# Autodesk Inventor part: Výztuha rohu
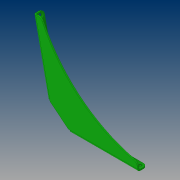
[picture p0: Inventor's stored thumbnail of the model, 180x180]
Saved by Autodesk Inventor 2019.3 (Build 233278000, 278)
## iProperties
Created: 2019-02
Part Number: Výztuha rohu
Material: Ocel, měkká, svařovaná
Document SubType Name: Plech
Designer: B-hon
Density: 7.85 g/cm^3
Sheet Metal Rule: Výchozí_mm
Appearance: Tmavě zelená
Author: B-hon
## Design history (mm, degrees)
node "Plocha2"
  sketch "Náčrt1"
    geometry: L1 (0, 0)-(-10.396, 48.907); L2 (0, 0)-(50, 0); L3 (-51.978, 244.537)-(-37.306, 247.656); L4 (0, 0)-(226.092, 279.201); L5 (250, 0)-(250, 15); L6 (50, 0)-(50, -8); L7 (50, -8)-(250, -8); L8 (250, -8)-(250, 0); L9 (-10.396, 48.907)-(-18.221, 47.244); L10 (-18.221, 47.244)-(-59.803, 242.874); L11 (-59.803, 242.874)-(-51.978, 244.537); L12 (-51.978, 244.537)-(148.022, 244.537); A1 r 400 centre (329.584, 407.003) between (-37.306, 247.656) and (250, 15)
    constraints: 24 end point, 2 horizontal, 2 parallel, 2 point on circle, 1 centre point, 1 perpendicular, 1 point on line, 1 vertical
    dimensions: "d0" = 250 distance of L1.start L5.start; "d1" = 250 distance of L1.start L3.start; "d2" = 102 deg angle of L2 L1; "d3" = 15 distance of L3.start L3.end; "d5" = 51 deg angle of L2 L4 (= 0.5 x d2); "d6" = 400 radius of A1; "d39" = 200 distance of L7.end L6.end; "d40" = 8 distance of L2.end L6.end; "d41" = 200 distance of L1.end L3.start; "d43" = 8 distance of L1.end L9.end (= d40)
node "Obruba4"
node "Obruba5"
chamfer "Zkosení1" distance "d68" = 45; stored, may be unused: second distance "d69" = 2, angle "d70" = 45 deg
fillet "Zaoblení3" dims "d71" = 10
fillet "Zaoblení4" dims "d72" = 10
fillet "Zaoblení5" dims "d73" = 15
sketch "Náčrt9"
  geometry: A1 r 10 centre (190, 10) between (200, 10) and (190, 20) reference; A2 r 10 centre (10, 10) between (10, 20) and (0, 10) reference; 3 further points
  constraints: 2 coincident
hole "Díra1" sketch "Náčrt9" at (190, 10), (10, 10) diameter "d74" = 8.4; stored, may be unused: countersink angle "d78" = 90 deg, drill point angle "d80" = 118 deg; dims "d75" = 12, "d76" = 15.4, "d77" = 2, "d79" = 4 (= Tloušťka)
sketch "Náčrt10"
  geometry: A1 r 10 centre (10, -10) between (20, -10) and (10, 0) reference; A2 r 10 centre (10, -190) between (10, -200) and (20, -190) reference; 3 further points
  constraints: 2 coincident
hole "Díra2" sketch "Náčrt10" at (10, -10), (10, -190) diameter "d81" = 8.4; stored, may be unused: countersink angle "d85" = 90 deg, drill point angle "d87" = 118 deg; dims "d82" = 12, "d83" = 15.4, "d84" = 2, "d86" = 4 (= Tloušťka)
sketch "Náčrt11"
  geometry: L1 (190, 20)-(10, 20) reference; L2 (200, 0)-(200, 10) reference; 2 further points
  dimensions: "d88" = 10 distance from line of L1 point (140, 10); "d89" = 60 distance from line of L2 point (140, 10)
hole "Díra3" sketch "Náčrt11" at (140, 10) diameter "d90" = 8.4; stored, may be unused: countersink angle "d94" = 90 deg, drill point angle "d96" = 118 deg; dims "d91" = 12, "d92" = 15.4, "d93" = 2, "d95" = 4 (= Tloušťka)
sketch "Náčrt12"
  geometry: L1 (0, 0)-(10, 0) reference; L2 (20, -190)-(20, -10) reference; 2 further points
  dimensions: "d97" = 60 distance from line of L1 point (10, -60); "d98" = 10 distance from line of L2 point (10, -60)
hole "Díra4" sketch "Náčrt12" at (10, -60) diameter "d99" = 8.4; stored, may be unused: countersink angle "d103" = 90 deg, drill point angle "d105" = 118 deg; dims "d100" = 12, "d101" = 15.4, "d102" = 2, "d104" = 4 (= Tloušťka)
node "Těleso2"
feature "Deska5" dims "d44" = 4 (= Tloušťka)
sketch "Náčrt7"
  geometry: L1 through (100, 0) direction (-1, 0); L2 through (0, -14) direction (0, -1); L3 (0, -28)-(200, -28); L4 (200, -28)-(200, 0)
  constraints: 6 end point, 1 horizontal, 1 perpendicular, 1 vertical
feature "Deska6" dims "d44" = 4 (= Tloušťka), "d46" = 4 (= ŠířkaVýštipu), "d47" = 2 (= HloubkaVýštipu), "d48" = 8 (= MinimálníZbytek), "d49" = 4 (= PřechodovýPoloměr), "d50" = 28, "d51" = 90 deg, "d52" = 4 (= PoloměrOhybu), "d53" = 16 (= VelikostRohovéhoVýštipu), "d54" = 4 (= VelikostMezery), "d55" = 4 (= VelikostJacobihoPoloměru), "MezeraVystřižení" = 0.01
feature "Ohyb4" dims "d44" = 4 (= Tloušťka), "d46" = 4 (= ŠířkaVýštipu), "d47" = 2 (= HloubkaVýštipu), "d48" = 8 (= MinimálníZbytek), "d49" = 4 (= PřechodovýPoloměr), "d50" = 28, "d51" = 90 deg, "d52" = 4 (= PoloměrOhybu), "MezeraVystřižení" = 0.01
feature "Roh4" dims "d50" = 28, "d51" = 90 deg, "d53" = 16 (= VelikostRohovéhoVýštipu), "d54" = 4 (= VelikostMezery), "d55" = 4 (= VelikostJacobihoPoloměru)
sketch "Náčrt8"
  geometry: L1 through (100, 0) direction (-1, 2.47e-33); L2 through (0, -14) direction (0, -1); L3 (0, -28)-(200, -28); L4 (200, -28)-(200, 0)
  constraints: 6 end point, 1 horizontal, 1 perpendicular, 1 vertical
feature "Deska7" dims "d44" = 4 (= Tloušťka), "d56" = 4 (= ŠířkaVýštipu), "d57" = 2 (= HloubkaVýštipu), "d58" = 8 (= MinimálníZbytek), "d59" = 4 (= PřechodovýPoloměr), "d60" = 28, "d61" = 90 deg, "d62" = 4 (= PoloměrOhybu), "d63" = 16 (= VelikostRohovéhoVýštipu), "d64" = 4 (= VelikostMezery), "d65" = 4 (= VelikostJacobihoPoloměru), "MezeraVystřižení" = 0.01
feature "Ohyb5" dims "d44" = 4 (= Tloušťka), "d56" = 4 (= ŠířkaVýštipu), "d57" = 2 (= HloubkaVýštipu), "d58" = 8 (= MinimálníZbytek), "d59" = 4 (= PřechodovýPoloměr), "d60" = 28, "d61" = 90 deg, "d62" = 4 (= PoloměrOhybu), "MezeraVystřižení" = 0.01
feature "Roh5" dims "d60" = 28, "d61" = 90 deg, "d63" = 16 (= VelikostRohovéhoVýštipu), "d64" = 4 (= VelikostMezery), "d65" = 4 (= VelikostJacobihoPoloměru)
other parameters: "Tloušťka" = 4 (derived), "KSoučinitel" = 4.4, "PoloměrOhybu" = 4 (derived), "ŠířkaVýštipu" = 4 (= Tloušťka), "HloubkaVýštipu" = 2 (= 0.5 x Tloušťka), "VelikostRohovéhoVýštipu" = 16 (= 4 x Tloušťka), "MinimálníZbytek" = 8 (= 2 x Tloušťka), "PřechodovýPoloměr" = 4 (= PoloměrOhybu), "VelikostJacobihoPoloměru" = 4 (= PoloměrOhybu), "VelikostMezery" = 4 (= Tloušťka)
